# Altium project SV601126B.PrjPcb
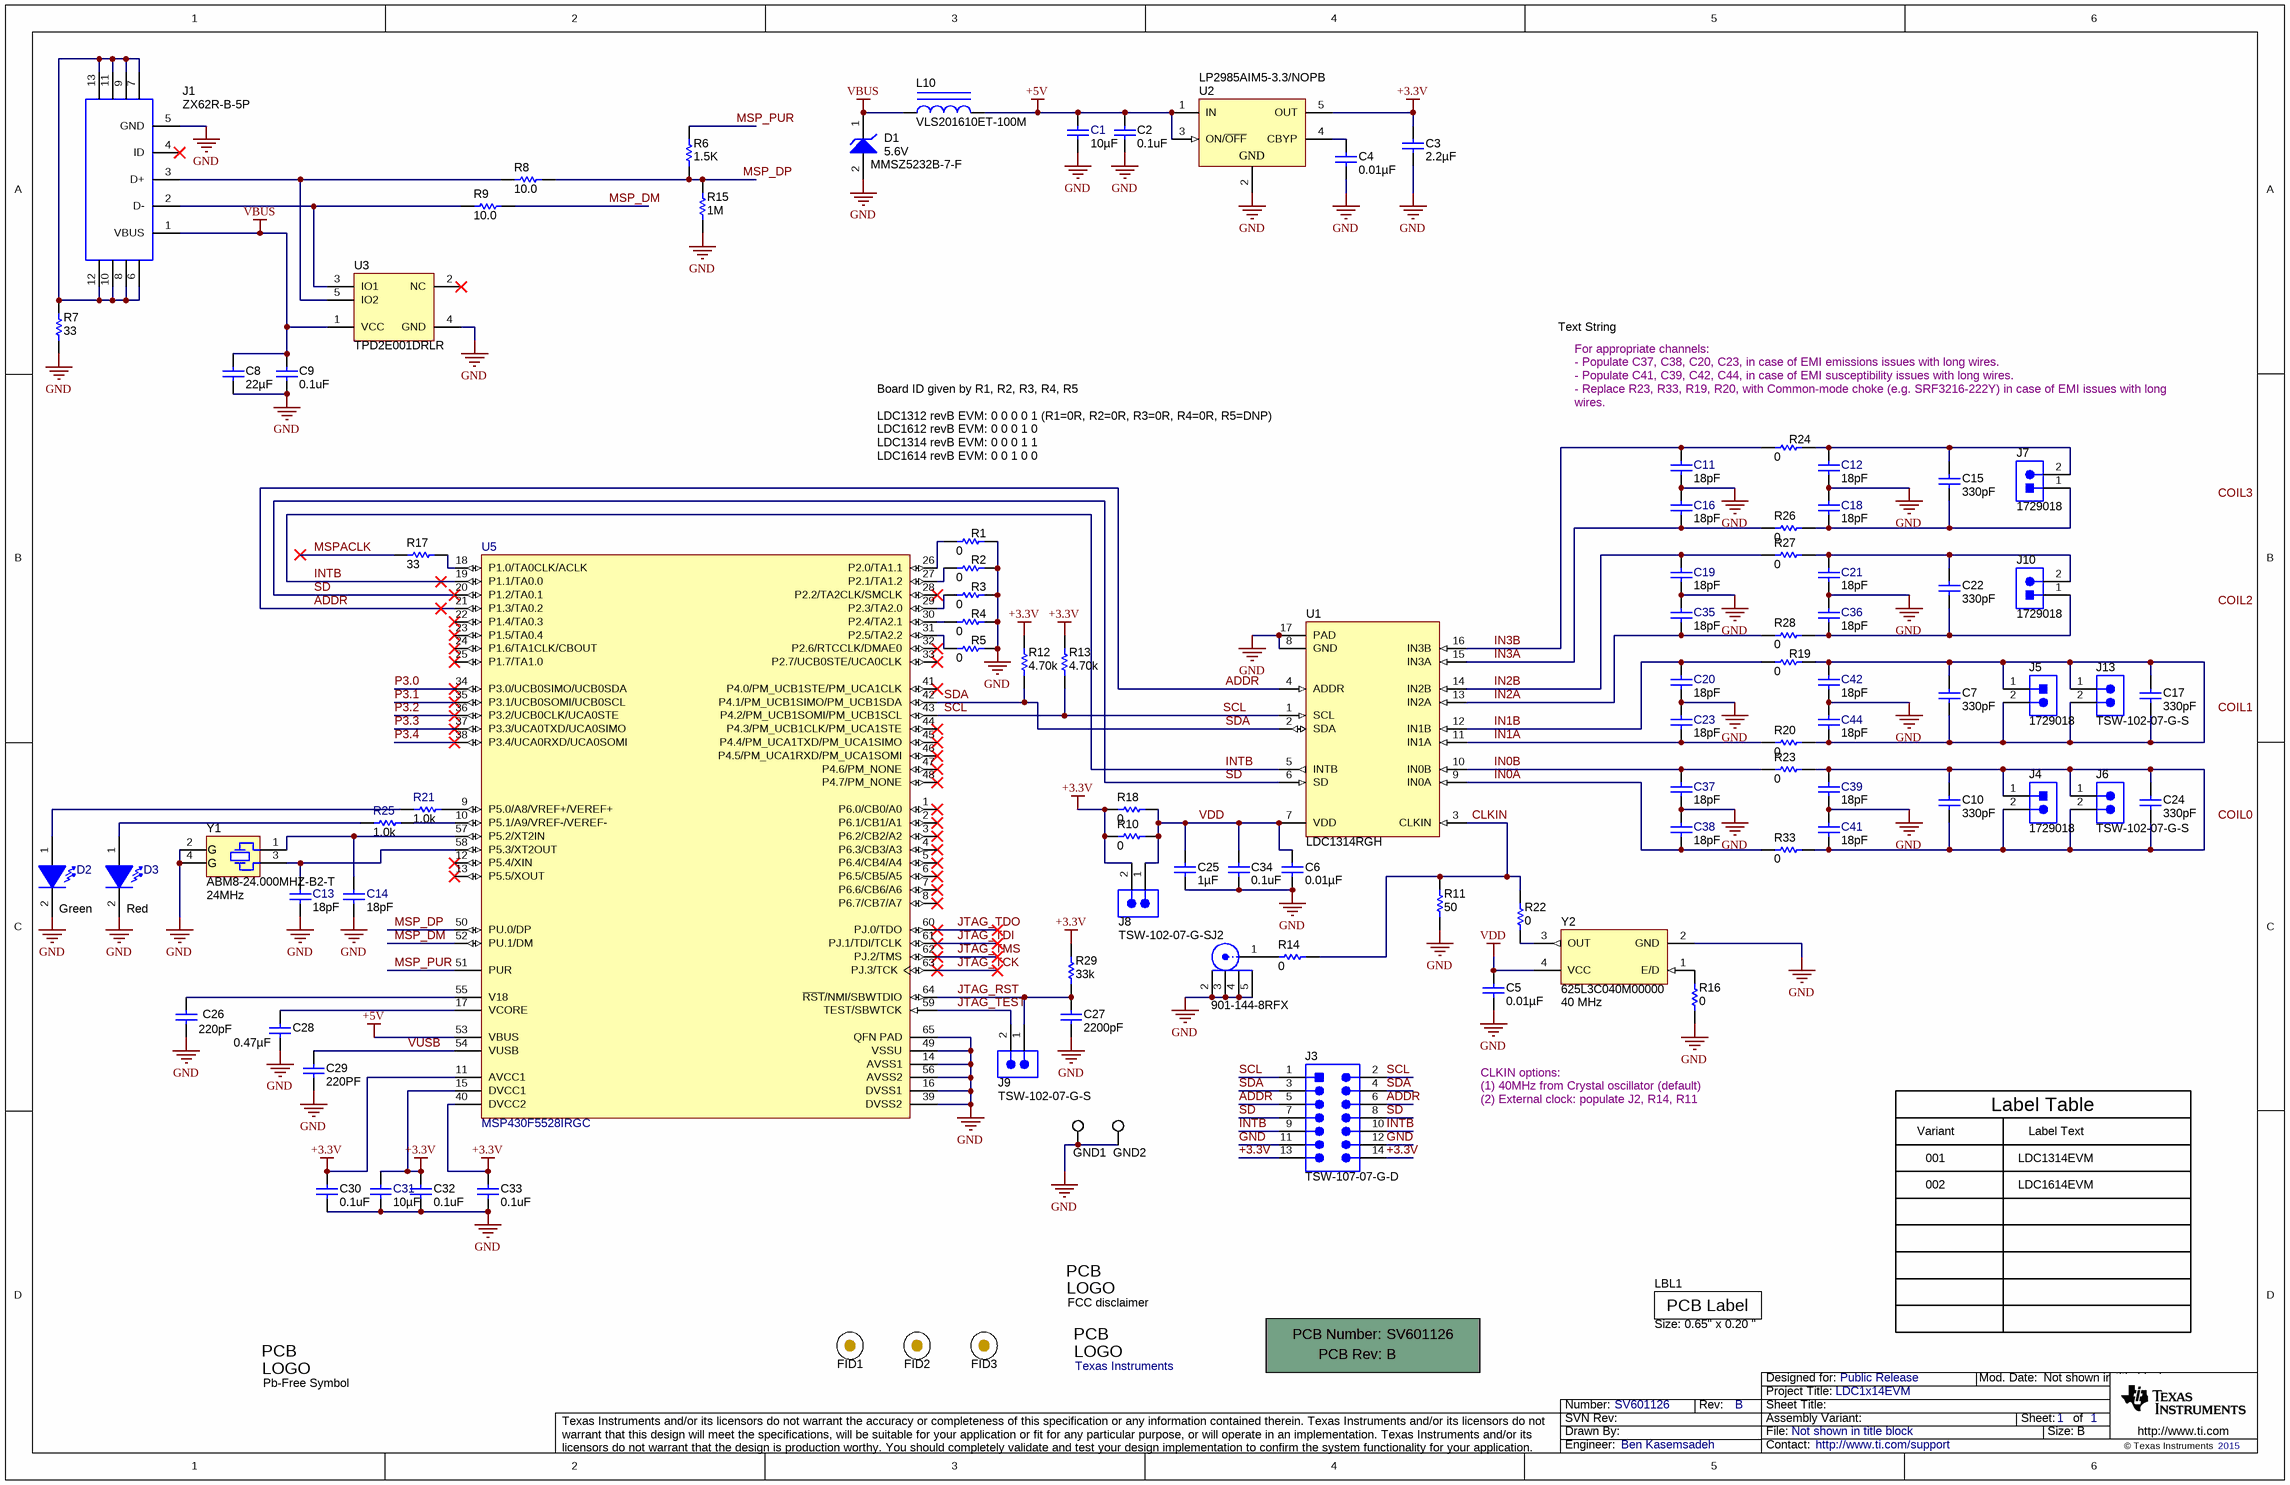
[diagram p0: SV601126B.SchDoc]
CopyrightYear: 2015; PCB_Layout: Ben Kasemsadeh; PCB_Rev: B; PRJ_Customer: Public Release; PRJ_Engineer: Ben Kasemsadeh; PRJ_Number: SV601126; PRJ_Title: LDC1x14EVM; SCH_Rev: B; TechSupport: http://www.ti.com/support
1 sheet, 103 parts. Net scope: global (net labels, ports and power ports of the same name join across sheets).
Board file: SV601126B.PcbDoc

## Sheet SV601126B.SchDoc
size 431 x 279 mm; Date: Not shown in title block; ApprovedBy: Not shown in title block; CheckedBy: Not shown in title block; Author: Not shown in title block; CompanyName: Not shown in title block; Engineer: Not shown in title block; Organization: Not shown in title block; Address1: Not shown in title block; Address2: Not shown in title block; Address3: Not shown in title block; Address4: Not shown in title block; DocumentNumber: 1; Revision: Use project parameter SCH_Rev; SheetNumber: 1; SheetTotal: 1; PageSetup: Record=PageOptions¦CenterHorizontal=True¦CenterVertical=True¦PrintScale=0.64¦XCorrection=1.00¦YCorrection=1.00¦PrintKind=0¦BorderSize=5000000¦LeftOffset=0¦BottomOffset=0¦Orientation=2¦PaperLength=1000¦PaperWidth=1000¦Scale=100¦PaperSource=15¦PrintQuality=600¦MediaType=1¦DitherType=10¦PaperKind=Letter¦PrintScaleMode=1

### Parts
!PCB1  Printed Circuit Board  (value not drawn)  (mechanical)
C1  ValueDisplayed: 10µF  [0603]  (hidden comment: C1608X5R1A106M)
C2  value 0.1uF  [0402]  (hidden comment: GRM155R71C104JA88D)
C3  ValueDisplayed: 2.2µF  [0603]  (hidden comment: C0603C225K8PACTU)
C4  ValueDisplayed: 0.01µF  [0603]  (hidden comment: C1608C0G1E103J)
C5  ValueDisplayed: 0.01µF  [0603]  (hidden comment: C1608C0G1E103J)
C6  ValueDisplayed: 0.01µF  [0402]  (hidden comment: C1005X7R1C103K)
C7  ValueDisplayed: 330pF  [0603]  (hidden comment: C1608C0G1H331F080AA)
C8  ValueDisplayed: 22µF  [0805_HV]  (hidden comment: C2012X5R1C226K125AC)
C9  value 0.1uF  [0402]  (hidden comment: GRM155R71C104JA88D)
C10  ValueDisplayed: 330pF  [0603]  (hidden comment: C1608C0G1H331F080AA)
C11  ValueDisplayed: 18pF  [0603]  (hidden comment: GRM1885C2A180JA01D)
C12  ValueDisplayed: 18pF  [0603]  (hidden comment: GRM1885C2A180JA01D)
C13  ValueDisplayed: 18pF  [0603]  (hidden comment: GRM1885C2A180JA01D)
C14  ValueDisplayed: 18pF  [0603]  (hidden comment: GRM1885C2A180JA01D)
C15  ValueDisplayed: 330pF  [0603]  (hidden comment: C1608C0G1H331F080AA)
C16  ValueDisplayed: 18pF  [0603]  (hidden comment: GRM1885C2A180JA01D)
C17  ValueDisplayed: 330pF  [0603]  (hidden comment: C1608C0G1H331F080AA)
C18  ValueDisplayed: 18pF  [0603]  (hidden comment: GRM1885C2A180JA01D)
C19  ValueDisplayed: 18pF  [0603]  (hidden comment: GRM1885C2A180JA01D)
C20  ValueDisplayed: 18pF  [0603]  (hidden comment: GRM1885C2A180JA01D)
C21  ValueDisplayed: 18pF  [0603]  (hidden comment: GRM1885C2A180JA01D)
C22  ValueDisplayed: 330pF  [0603]  (hidden comment: C1608C0G1H331F080AA)
C23  ValueDisplayed: 18pF  [0603]  (hidden comment: GRM1885C2A180JA01D)
C24  ValueDisplayed: 330pF  [0603]  (hidden comment: C1608C0G1H331F080AA)
C25  ValueDisplayed: 1µF  [0402]  (hidden comment: GRM155R61A105KE15D)
C26  ValueDisplayed: 220pF  [0603]  (hidden comment: 06035A221FAT2A)
C27  ValueDisplayed: 2200pF  [0603]  (hidden comment: C0603X222K5RACTU)
C28  ValueDisplayed: 0.47µF  [0603]  (hidden comment: C0603C474K8RACTU)
C29  value 220PF  [0402]  (hidden comment: C1005C0G1H221F050BA)
C30  value 0.1uF  [0402]  (hidden comment: GRM155R71C104JA88D)
C31  ValueDisplayed: 10µF  [0603]  (hidden comment: C1608X5R1A106M)
C32  value 0.1uF  [0402]  (hidden comment: GRM155R71C104JA88D)
C33  value 0.1uF  [0402]  (hidden comment: GRM155R71C104JA88D)
C34  value 0.1uF  [0402]  (hidden comment: GRM155R71C104JA88D)
C35  ValueDisplayed: 18pF  [0603]  (hidden comment: GRM1885C2A180JA01D)
C36  ValueDisplayed: 18pF  [0603]  (hidden comment: GRM1885C2A180JA01D)
C37  ValueDisplayed: 18pF  [0603]  (hidden comment: GRM1885C2A180JA01D)
C38  ValueDisplayed: 18pF  [0603]  (hidden comment: GRM1885C2A180JA01D)
C39  ValueDisplayed: 18pF  [0603]  (hidden comment: GRM1885C2A180JA01D)
C41  ValueDisplayed: 18pF  [0603]  (hidden comment: GRM1885C2A180JA01D)
C42  ValueDisplayed: 18pF  [0603]  (hidden comment: GRM1885C2A180JA01D)
C44  ValueDisplayed: 18pF  [0603]  (hidden comment: GRM1885C2A180JA01D)
D1  MMSZ5232B-7-F  value 5.6V  [SOD-123]
D2  value Green  [LG L29K_GREEN]  (hidden comment: LG L29K-G2J1-24-Z)
D3  value Red  [SML-LX0603SRW_SuperRed]  (hidden comment: SML-LX0603SRW-TR)
FID1  Fiducial  [Fiducial10-20]  (value not drawn)
FID2  Fiducial  [Fiducial10-20]  (value not drawn)
FID3  Fiducial  [Fiducial10-20]  (value not drawn)
GND1  5015  [Testpoint_Keystone_Miniature]  (value not drawn)
GND2  5015  [Testpoint_Keystone_Miniature]  (value not drawn)
J1  ZX62R-B-5P  [Hirose_ZX62R-B-5P]
J2  901-144-8RFX  [Amphenol_901-144-8RFX]
J3  TSW-107-07-G-D  [TSW-107-07-G-D]
J4  1729018  [Phoenix_1729018]
J5  1729018  [Phoenix_1729018]
J6  TSW-102-07-G-S  [TSW-102-07-G-S]
J7  1729018  [Phoenix_1729018]
J8  TSW-102-07-G-S  [TSW-102-07-G-S]
J9  TSW-102-07-G-S  [TSW-102-07-G-S]
J10  1729018  [Phoenix_1729018]
J13  TSW-102-07-G-S  [TSW-102-07-G-S]
L10  VLS201610ET-100M  [VLS201610ET]
LBL1  Size: 0.65" x 0.20 "  [Label_650x200]
Logo1  Texas Instruments  [TI_Stacked_Overlay_Small]  (no BOM)
Logo2  FCC disclaimer  [FCC_disclaimer_stacked]  (no BOM)
Logo3  Pb-Free Symbol  [Pb-Free_Overlay_Medium]  (no BOM)
R1  value 0  [0603]  (hidden comment: CRCW06030000Z0EA)
R2  value 0  [0603]  (hidden comment: CRCW06030000Z0EA)
R3  value 0  [0603]  (hidden comment: CRCW06030000Z0EA)
R4  value 0  [0603]  (hidden comment: CRCW06030000Z0EA)
R5  value 0  [0603]  (hidden comment: CRCW06030000Z0EA)
R6  value 1.5K  [0402]  (hidden comment: CRCW04021K50JNED)
R7  value 33  [0603]  (hidden comment: CRCW060333R0JNEA)
R8  ValueDisplayed: 10.0  [0402]  (hidden comment: CRCW040210R0FKED)
R9  ValueDisplayed: 10.0  [0402]  (hidden comment: CRCW040210R0FKED)
R10  value 0  [0603]  (hidden comment: CRCW06030000Z0EA)
R11  ValueDisplayed: 50  [0603]  (hidden comment: CRCW060350R0FKEA)
R12  value 4.70k  [0603]  (hidden comment: RC0603FR-074K7L)
R13  value 4.70k  [0603]  (hidden comment: RC0603FR-074K7L)
R14  value 0  [0603]  (hidden comment: CRCW06030000Z0EA)
R15  value 1M  [0402]  (hidden comment: RC0402JR-071ML)
R16  value 0  [0603]  (hidden comment: CRCW06030000Z0EA)
R17  value 33  [0603]  (hidden comment: CRCW060333R0JNEA)
R18  value 0  [0603]  (hidden comment: CRCW06030000Z0EA)
R19  value 0  [0805_HV]  (hidden comment: CRCW08050000Z0EA)
R20  value 0  [0805_HV]  (hidden comment: CRCW08050000Z0EA)
R21  value 1.0k  [0402]  (hidden comment: CRCW04021K00JNED)
R22  value 0  [0603]  (hidden comment: CRCW06030000Z0EA)
R23  value 0  [0805_HV]  (hidden comment: CRCW08050000Z0EA)
R24  value 0  [0805_HV]  (hidden comment: CRCW08050000Z0EA)
R25  value 1.0k  [0402]  (hidden comment: CRCW04021K00JNED)
R26  value 0  [0805_HV]  (hidden comment: CRCW08050000Z0EA)
R27  value 0  [0805_HV]  (hidden comment: CRCW08050000Z0EA)
R28  value 0  [0805_HV]  (hidden comment: CRCW08050000Z0EA)
R29  value 33k  [0402]  (hidden comment: CRCW040233K0JNED)
R33  value 0  [0805_HV]  (hidden comment: CRCW08050000Z0EA)
U1  LDC1314RGH  [RGH0016A]
U2  LP2985AIM5-3.3/NOPB  [MF05A_N]
U3  TPD2E001DRLR  [DRL0005A]
U5  MSP430F5528IRGC  [RGC0064B]
Y1  ABM8-24.000MHZ-B2-T  Frequency: 24MHz  [XTAL_ABM8]
Y2  625L3C040M00000  Frequency: 40 MHz  [OSC_CTS_625]

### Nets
+3.3V: C3.1 C30.1 C31.1 C32.1 C33.1 J3.13 J3.14 J8.2 R10.1 R12.2 R13.2 R18.1 R29.1 U2.5(OUT) U5.11(AVCC1) U5.15(DVCC1) U5.40(DVCC2)
+5V: C1.1 C2.1 L10.2 U2.1(IN) U2.3(ON/~{OFF}) U5.53(VBUS)
GND: C1.2 C2.2 C3.2 C4.2 C5.2 C6.2 C8.2 C9.2 C11.1 C12.1 C13.1 C14.1 C16.2 C18.2 C19.1 C20.1 C21.1 C23.2 C25.2 C26.1 C27.1 C28.2 C29.2 C30.2 C31.2 C32.2 C33.2 C34.2 C35.2 C36.2 C37.1 C38.2 C39.1 C41.2 C42.1 C44.2 D1.2(A) D2.2(K) D3.2(K) GND1.1 GND2.1 J1.5(GND) J2.2 J2.3 J2.4 J2.5 J3.11 J3.12 R1.2 R2.2 R3.2 R4.2 R5.2 R7.1 R11.1 R15.1 R16.1 U1.8(GND) U1.17(PAD) U2.2(GND) U3.4(GND) U5.14(AVSS1) U5.16(DVSS1) U5.39(DVSS2) U5.49(VSSU) U5.56(AVSS2) U5.65(QFN_PAD) Y1.2(GND) Y1.4(GND) Y2.2(GND)
VBUS: C8.1 C9.1 D1.1(K) J1.1(VBUS) L10.1 U3.1(VCC)
VDD: C5.1 C6.1 C25.1 C34.1 J8.1 R10.2 R18.2 U1.7(VDD) Y2.4(VCC)
ADDR: J3.5 J3.6 U1.4(ADDR) U5.21(P1.3/TA0.2)
CLKIN: R11.2 R14.2 R22.2 U1.3(CLKIN)
IN0A: C38.1 R33.1 U1.9(IN0A)
IN0B: C37.2 R23.1 U1.10(IN0B)
IN1A: C23.1 R20.1 U1.11(IN1A)
IN1B: C20.2 R19.1 U1.12(IN1B)
IN2A: C35.1 R28.1 U1.13(IN2A)
IN2B: C19.2 R27.1 U1.14(IN2B)
IN3A: C16.1 R26.1 U1.15(IN3A)
IN3B: C11.2 R24.1 U1.16(IN3B)
INTB: J3.9 J3.10 U1.5(INTB) U5.19(P1.1/TA0.0)
JTAG_RST: C27.2 J9.1 R29.2 U5.64(~{RST}/NMI/SBWTDIO)
JTAG_TCK: U5.63(PJ.3/TCK)
JTAG_TDI: U5.61(PJ.1/TDI/TCLK)
JTAG_TDO: U5.60(PJ.0/TDO)
JTAG_TEST: J9.2 U5.59(TEST/SBWTCK)
JTAG_TMS: U5.62(PJ.2/TMS)
MSP_DM: R9.2 U5.52(PU.1/DM)
MSP_DP: R6.1 R8.2 R15.2 U5.50(PU.0/DP)
MSP_PUR: R6.2 U5.51(PUR)
MSPACLK: R17.2
P3.0: U5.34(P3.0/UCB0SIMO/UCB0SDA)
P3.1: U5.35(P3.1/UCB0SOMI/UCB0SCL)
P3.2: U5.36(P3.2/UCB0CLK/UCA0STE)
P3.3: U5.37(P3.3/UCA0TXD/UCA0SIMO)
P3.4: U5.38(P3.4/UCA0RXD/UCA0SOMI)
SCL: J3.1 J3.2 R13.1 U1.1(SCL) U5.43(P4.2/PM_UCB1SOMI/PM_UCB1SCL)
SD: J3.7 J3.8 U1.6(SD) U5.20(P1.2/TA0.1)
SDA: J3.3 J3.4 R12.1 U1.2(SDA) U5.42(P4.1/PM_UCB1SIMO/PM_UCB1SDA)
VUSB: C29.1 U5.54(VUSB)
NetC4_1: C4.1 U2.4(CBYP)
NetC7_1: C7.1 C7.2 C17.1 C17.2 C42.2 C44.1 J5.1 J5.2 J13.1 J13.2 R19.2 R20.2
NetC10_1: C10.1 C10.2 C24.1 C24.2 C39.2 C41.1 J4.1 J4.2 J6.1 J6.2 R23.2 R33.2
NetC12_2: C12.2 C15.1 J7.2 R24.2
NetC13_2: C13.2 U5.58(P5.3/XT2OUT) Y1.3
NetC14_2: C14.2 U5.57(P5.2/XT2IN) Y1.1
NetC15_2: C15.2 C18.1 J7.1 R26.2
NetC21_2: C21.2 C22.1 J10.2 R27.2
NetC22_2: C22.2 C36.1 J10.1 R28.2
NetC26_2: C26.2 U5.55(V18)
NetC28_1: C28.1 U5.17(VCORE)
NetD2_1: D2.1(A) R21.2
NetD3_1: D3.1(A) R25.2
NetJ1_2: J1.2(D-) R9.1 U3.3(IO1)
NetJ1_3: J1.3(D+) R8.1 U3.5(IO2)
NetJ1_6: J1.6 J1.7 J1.8 J1.9 J1.10 J1.11 J1.12 J1.13 R7.2
NetJ2_1: J2.1 R14.1
NetR1_1: R1.1 U5.26(P2.0/TA1.1)
NetR2_1: R2.1 U5.27(P2.1/TA1.2)
NetR3_1: R3.1 U5.29(P2.3/TA2.0)
NetR4_1: R4.1 U5.30(P2.4/TA2.1)
NetR5_1: R5.1 U5.31(P2.5/TA2.2)
NetR16_2: R16.2 Y2.1(E/D)
NetR17_1: R17.1 U5.18(P1.0/TA0CLK/ACLK)
NetR21_1: R21.1 U5.9(P5.0/A8/VREF+/VEREF+)
NetR22_1: R22.1 Y2.3(OUT)
NetR25_1: R25.1 U5.10(P5.1/A9/VREF-/VEREF-)

Not connected (* = marked no-connect by the designer): J1 4(ID)*; U3 2(NC)*; U5 1(P6.0/CB0/A0)* 2(P6.1/CB1/A1)* 3(P6.2/CB2/A2)* 4(P6.3/CB3/A3)* 5(P6.4/CB4/A4)* 6(P6.5/CB5/A5)* 7(P6.6/CB6/A6)* 8(P6.7/CB7/A7)* 12(P5.4/XIN)* 13(P5.5/XOUT)* 22(P1.4/TA0.3)* 23(P1.5/TA0.4)* 24(P1.6/TA1CLK/CBOUT)* 25(P1.7/TA1.0)* 28(P2.2/TA2CLK/SMCLK)* 32(P2.6/RTCCLK/DMAE0)* 33(P2.7/UCB0STE/UCA0CLK)* 41(P4.0/PM_UCB1STE/PM_UCA1CLK)* 44(P4.3/PM_UCB1CLK/PM_UCA1STE)* 45(P4.4/PM_UCA1TXD/PM_UCA1SIMO)* 46(P4.5/PM_UCA1RXD/PM_UCA1SOMI)* 47(P4.6/PM_NONE)* 48(P4.7/PM_NONE)*

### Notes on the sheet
- Text String
- For appropriate channels:
  - Populate C37, C38, C20, C23, in case of EMI emissions issues with long wires.
  - Populate C41, C39, C42, C44, in case of EMI susceptibility issues with long wires.
  - Replace R23, R33, R19, R20, with Common-mode choke (e.g. SRF3216-222Y) in case of EMI issues with long wires.
- Board ID given by R1, R2, R3, R4, R5
  LDC1312 revB EVM: 0 0 0 0 1 (R1=0R, R2=0R, R3=0R, R4=0R, R5=DNP)
  LDC1612 revB EVM: 0 0 0 1 0
  LDC1314 revB EVM: 0 0 0 1 1
  LDC1614 revB EVM: 0 0 1 0 0
- Label Table
- CLKIN options:
  (1) 40MHz from Crystal oscillator (default)
  (2) External clock: populate J2, R14, R11
- Variant
- 001
- Label Text
- LDC1314EVM
- 002
- LDC1614EVM
- Labels drawn without touching a wire or pin: COIL0, COIL1, COIL2, COIL3

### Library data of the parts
!PCB1 = PCB: Manufacturer: Any; PartNumber: SV601126; SymbolCreator: a0412235
C1 C31 = C1608X5R1A106M: CAP, CERM, 10uF, 10V, +/-20%, X5R, 0603; Manufacturer: TDK; Polarized: N; CompType: Capacitor; U/M: EA; Cap_F: 0.00001; Tolerance_%: 20; ESR_Ohm: 0.0078; Value1: 0.0078 ohm; VDC_V: 10; IRMS_A: 1.85; TaMin_C: -55; TaMax_C: 85
C2 C9 C30 C32-C34 = 0402YC132KAT2A: CAP CER 0.1UF 16V 5% X7R 0402; Manufacturer: Murata Electronics North America; Polarized: N; CompType: Capacitor; U/M: EA; Cap_F: 0.0000000013; Tolerance_%: 10; VDC_V: 16; TaMin_C: -55; TaMax_C: 125
C3 = C0603C225K8PACTU: CAP, CERM, 2.2uF, 10V, +/-10%, X5R, 0603; Manufacturer: Kemet; Polarized: N; CompType: Capacitor; U/M: EA; Cap_F: 0.0000022; Tolerance_%: 10; Value1: Unknown; TaMin_C: -55; TaMax_C: 85
C4 C5 = C1608C0G1E103J: CAP, CERM, 0.01uF, 25V, +/-5%, C0G/NP0, 0603; Manufacturer: TDK; Polarized: N; CompType: Capacitor; U/M: EA; Cap_F: 0.00000001; Tolerance_%: 5; VDC_V: 25; TaMin_C: -55; TaMax_C: 125
C6 = C1005X7R1C103K: CAP, CERM, 0.01 µF, 16 V, +/- 10%, X7R, 0402; Manufacturer: TDK; Polarized: N; CompType: Capacitor; Value: 0.01uF; U/M: EA; Cap_F: 0.00000001; Tolerance_%: 10; ESR_ohm: 0.0623; Value1: 0.0623 ohm; VDC_V: 16; Value2: 16V; TaMin_C: -55; TaMax_C: 125
C7 C10 C15 C17 C22 C24 = C1608C0G1H331F080AA: CAP, CERM, 330pF, 50V, +/-1%, C0G/NP0, 0603; Manufacturer: TDK; Polarized: N; CompType: Capacitor; U/M: EA; Cap_F: 0.00000000033; Tolerance_%: 1; Value1: Unknown; VDC_V: 50; TaMin_C: -55; TaMax_C: 125
C8 = C2012X5R1C226K125AC: CAP, CERM, 22uF, 16V, +/-10%, X5R, 0805; Manufacturer: TDK; Polarized: N; CompType: Capacitor; U/M: EA; Cap_F: 0.000022; Tolerance_%: 10; Value1: Unknown; VDC_V: 16; TaMin_C: -55; TaMax_C: 85; Cap_Case: 0805
C11-C14 C16 C18-C21 C23 C35-C39 C41 C42 C44 = GRM1885C2A180JA01D: CAP, CERM, 18pF, 100V, +/-5%, C0G/NP0, 0603; Manufacturer: MuRata; Polarized: N; CompType: Capacitor; U/M: EA; Cap_F: 0.000000000018; Tolerance_%: 5; Value1: Unknown; VDC_V: 100; TaMin_C: -55; TaMax_C: 125
C25 = GRM155R61A105KE15D: CAP, CERM, 1uF, 10V, +/-10%, X5R, 0402; Manufacturer: MuRata; Polarized: N; CompType: Capacitor; U/M: EA; Cap_F: 0.000001; Tolerance_%: 10; Value1: Unknown; TaMin_C: -55; TaMax_C: 85
C26 = 06035A221FAT2A: CAP, CERM, 220pF, 50V, +/-1%, C0G/NP0, 0603; Manufacturer: AVX; Polarized: N; CompType: Capacitor; U/M: EA; Cap_F: 0.00000000022; Tolerance_%: 1; ESR_Ohm: 0.083; Value1: 0.083 ohm; VDC_V: 50; TaMin_C: -55; TaMax_C: 125
C27 = C0603X222K5RACTU: CAP, CERM, 2200pF, 50V, +/-10%, X7R, 0603; Manufacturer: Kemet; Polarized: N; CompType: Capacitor; U/M: EA; Cap_F: 0.0000000022; Tolerance_%: 10; VDC_V: 50; TaMin_C: -55; TaMax_C: 125
C28 = C0603C474K8RACTU: CAP, CERM, 0.47uF, 10V, +/-10%, X7R, 0603; Manufacturer: Kemet; Polarized: N; CompType: Capacitor; U/M: EA; Cap_F: 0.00000047; Tolerance_%: 10; TaMin_C: -55; TaMax_C: 125
C29 = 0402YC132KAT2A: CAP CER 220PF 50V 1% NP0 0402; Manufacturer: TDK Corporation; Polarized: N; CompType: Capacitor; U/M: EA; Cap_F: 0.0000000013; Tolerance_%: 10; VDC_V: 16; TempCo: X7R; TaMin_C: -55; TaMax_C: 125
D1 = MMSZ5232B-7-F: Diode, Zener, 5.6V, 500mW, SOD-123; Manufacturer: Diodes Inc.; U/M: EA; Power_W: 0.5; Vz_V: 5.6; Value1: 0.5W; RJA_CperW: 350
D2 = LG L29K-G2J1-24-Z: LED, Green, SMD; Manufacturer: OSRAM; Vf_V: 1.7; Value2: 1.7V; Io_A: 0.002; Tjmax_C: 110; Value1: W; U/M: EA
D3 = SML-LX0603SRW-TR: LED, Super Red, SMD; Manufacturer: Lumex; Vf_V: 1.7; Value2: 1.7V; Io_A: 0.02; Value1: W; U/M: EA
FID1-FID3 = Fiducial: Fiducial mark.  There is nothing to buy or mount.; SymbolCreator: codlsc
GND1 GND2 = 5015: Test Point, Miniature, SMT; Manufacturer: Keystone; CompType: Test Point Loop; U/M: EA
J1 = ZX62R-B-5P: Connector, Receptacle, Micro-USB Type B, SMT; Manufacturer: Hirose Electric Co. Ltd.; SymbolCreator: a0799628; U/M: EA
J2 = 901-144-8RFX: SMA Straight Jack, Gold, 50 Ohm, TH; Manufacturer: Amphenol RF; SymbolCreator: X0208326; U/M: EA
J3 = TSW-107-07-G-D: Header, 100mil, 7x2, Gold, TH; Manufacturer: Samtec; SymbolCreator: a0412235; U/M: EA
J4 J5 J7 J10 = 1729018: TERM BLOCK 2POS 5mm, TH; Manufacturer: Phoenix Contact; SymbolCreator: a0412235; CompType: Header; U/M: EA
J6 J8 J9 J13 = TSW-102-07-G-S: Header, TH, 100mil, 2x1, Gold plated, 230 mil above insulator; Manufacturer: Samtec, Inc.; SymbolCreator: a0412235; U/M: EA
L10 = VLS201610ET-100M: Inductor, Shielded, Ferrite, 10 µH, 0.4 A, 1.38 ohm, SMD; Manufacturer: TDK; Value: 10uH; Ind_H: 10.0E-6; ValueDisplayed: 10µH; Imax_A: 0.4; Irms: 0.42A @ 40C rise; Isat: 0.4A @ 30% inductance drop; DCR_ohm: 1.38; Value2: 0.4A
LBL1 = THT-14-423-10: Thermal Transfer Printable Labels, 0.650" W x 0.200" H - 10,000 per roll; Manufacturer: Brady; SymbolCreator: a0412235; CompType: Label
Logo1 = TI_Logo: Texas Instrument Corporate Signature; SymbolCreator: codlsc
Logo2 = FCC_disclaimer: SymbolCreator: codlsc
Logo3 = Pb-Free: SymbolCreator: a0412235
R1-R5 R10 R14 R16 R18 R22 = CRCW06030000Z0EA: RES, 0 ohm, 5%, 0.1W, 0603; Manufacturer: Vishay-Dale; CompType: Resistor; Value_Code: 0000; Tolerance_%: 5; Power_W: 0.1; VDC_V: 75; TempCo: 200 ppm/C; EIA_Code: E24; U/M: EA
R6 = CRCW040233K0JNED: RES 1.5K OHM 1/16W 5% 0402 SMD; Manufacturer: Vishay Dale; CompType: Resistor; Res_ohm: 33000; Value_Code: 33k0; Tolerance_%: 5; Power_W: 0.063; Value2: 0.063W; VDC_V: 50; TempCo: 200 ppm/C; EIA_Code: E24; U/M: EA
R7 R17 = CRCW060333R0JNEA: RES, 33 ohm, 5%, 0.1W, 0603; Manufacturer: Vishay-Dale; CompType: Resistor; Value_Code: 33R0; Tolerance_%: 5; Power_W: 0.1; VDC_V: 75; TempCo: 200 ppm/C; EIA_Code: E24; U/M: EA
R8 R9 = CRCW040210R0FKED: RES, 10.0, 1%, 0.063 W, 0402; Manufacturer: Vishay-Dale; CompType: Resistor; Value: 10.0; Res_ohm: 10; Value_Code: 10R0; Tolerance_%: 1; Power_W: 0.063; Value2: 0.063W; VDC_V: 50; TempCo: 100 ppm/C; EIA_Code: E96; U/M: EA
R11 = CRCW060350R0FKEA: RES, 50, 1%, 0.1 W, 0603; Manufacturer: Vishay-Dale; CompType: Resistor; Value: 50; Value_Code: 50R0; Tolerance_%: 1; Power_W: 0.1; Value2: 0.1W; VDC_V: 75; TempCo: 100 ppm/C; U/M: EA
R12 R13 = RC0603FR-074K7L: RES, 4.70k ohm, 1%, 0.1W, 0603; Manufacturer: Yageo America; CompType: Resistor; Res_ohm: 4700; Value_Code: 4k70; Tolerance_%: 1; Power_W: 0.1; VDC_V: 150; TempCo: 200 ppm/C; U/M: EA
R15 = CRCW040233K0JNED: RES,1M ohm, 5%, 0.063W, 0402; Manufacturer: Yageo; CompType: Resistor; Res_ohm: 33000; Value_Code: 33k0; Tolerance_%: 5; Power_W: 0.063; VDC_V: 50; TempCo: 200 ppm/C; EIA_Code: E24; U/M: EA
R19 R20 R23 R24 R26-R28 R33 = CRCW08050000Z0EA: RES, 0 ohm, 5%, 0.125W, 0805; Manufacturer: Vishay-Dale; CompType: Resistor; Value_Code: 0000; Tolerance_%: 5; Power_W: 0.125; VDC_V: 150; TempCo: 200 ppm/C; EIA_Code: E24; U/M: EA
R21 R25 = CRCW04021K00JNED: RES, 1.0k ohm, 5%, 0.063W, 0402; Manufacturer: Vishay-Dale; CompType: Resistor; Res_ohm: 1000; Value_Code: 1k00; Tolerance_%: 5; Power_W: 0.063; VDC_V: 50; TempCo: 200 ppm/C; EIA_Code: E24; U/M: EA
R29 = CRCW040233K0JNED: RES, 33k ohm, 5%, 0.063W, 0402; Manufacturer: Vishay-Dale; CompType: Resistor; Res_ohm: 33000; Value_Code: 33k0; Tolerance_%: 5; Power_W: 0.063; VDC_V: 50; TempCo: 200 ppm/C; EIA_Code: E24; U/M: EA
U1 = LDC1314RGH: Multi-Channel 12/28-Bit Inductance to Digital Converter with I2C, RGH0016A; Manufacturer: Texas Instruments; SymbolCreator: a0411947; CompType: IC; U/M: EA
U2 = LP2985AIM5-3.3/NOPB: Micropower 150 mA Low-Noise Ultra Low-Dropout Regulator, 5-pin SOT-23, Pb-Free; Manufacturer: Texas Instruments; PackageTopMarking: L0RA*XTT; PowerWise: N; CompType: LDO IC
U3 = TPD2E001DRLR: Low-Capacitance + / - 15 kV ESD-Protection Array for High-Speed Data Interfaces, 2 Channels, -40 to +85 degC, 5-pin SOT (DRL), Green (RoHS & no Sb/Br); Manufacturer: Texas Instruments; Alternate Manufacturer: None; Alternate PartNumber: Equivalent; Breakdown Voltage(Min)(V): 11; IEC 61000-4-2 Air-Gap(+/- kV): 15; IEC 61000-4-2 Contact(+/- kV): 8; IO Capacitance(Typ)(pF): 1.5; IO Leakage Current(nA): 1; SubFamily: ESD Solution; USB High Speed: TRUE
U5 = MSP430F5528IRGC: Mixed Signal MicroController, RGC0064B; Manufacturer: Texas Instruments; Alternate Manufacturer: None; ADC: 12-bit SAR; ADC Channels: 16; Brown Out Reset: Yes; DMA: 3; Eco-Plan: Green (RoHS & no Sb/Br); Flash(KB): 128; Frequency(MHz): 25; GPIO: 47; Multiplier: 32x32; SRAM(B): 8192; SubFamily: 5 Series; Timers - 16-bit: 4; USB: 1; USCI_A (UART/LIN/IrDA/SPI): 2; SymbolCreator: Altium/a0412235; CompType: IC; U/M: EA
Y1 = ABM8-24.000MHZ-B2-T: Crystal, 24.000MHz, 18pF, SMD; Manufacturer: Abracon Corportation; SymbolCreator: a0412235; U/M: EA; TaMin_C: -20; TaMax_C: 70; Frequency Stability: ±50ppm
Y2 = 625L3C040M00000: OSC, 40 MHz, 3.3 V, SMD; Manufacturer: CTS Electrocomponents; SymbolCreator: a0411947; CompType: Oscillator; U/M: EA; TaMin_C: -20; TaMax_C: 70; Frequency Stability: ±50ppm

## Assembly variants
001: not fitted C7 C10 C11 C12 C15 C16 C18 C19 C20 C21 C22 C23 C35 C36 C37 C38 C39 C41 C42 C44 FID1 FID2 FID3 J2 J3 J4 J5 J6 J7 J8 J9 J10 J13 R4 R5 R11 R14 R16
002: not fitted C7 C10 C11 C12 C15 C16 C18 C19 C20 C21 C22 C23 C35 C36 C37 C38 C39 C41 C42 C44 FID1 FID2 FID3 J2 J3 J4 J5 J6 J7 J8 J9 J10 J13 R3 R11 R14 R16; alternate parts U1 -> LDC1614RGH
